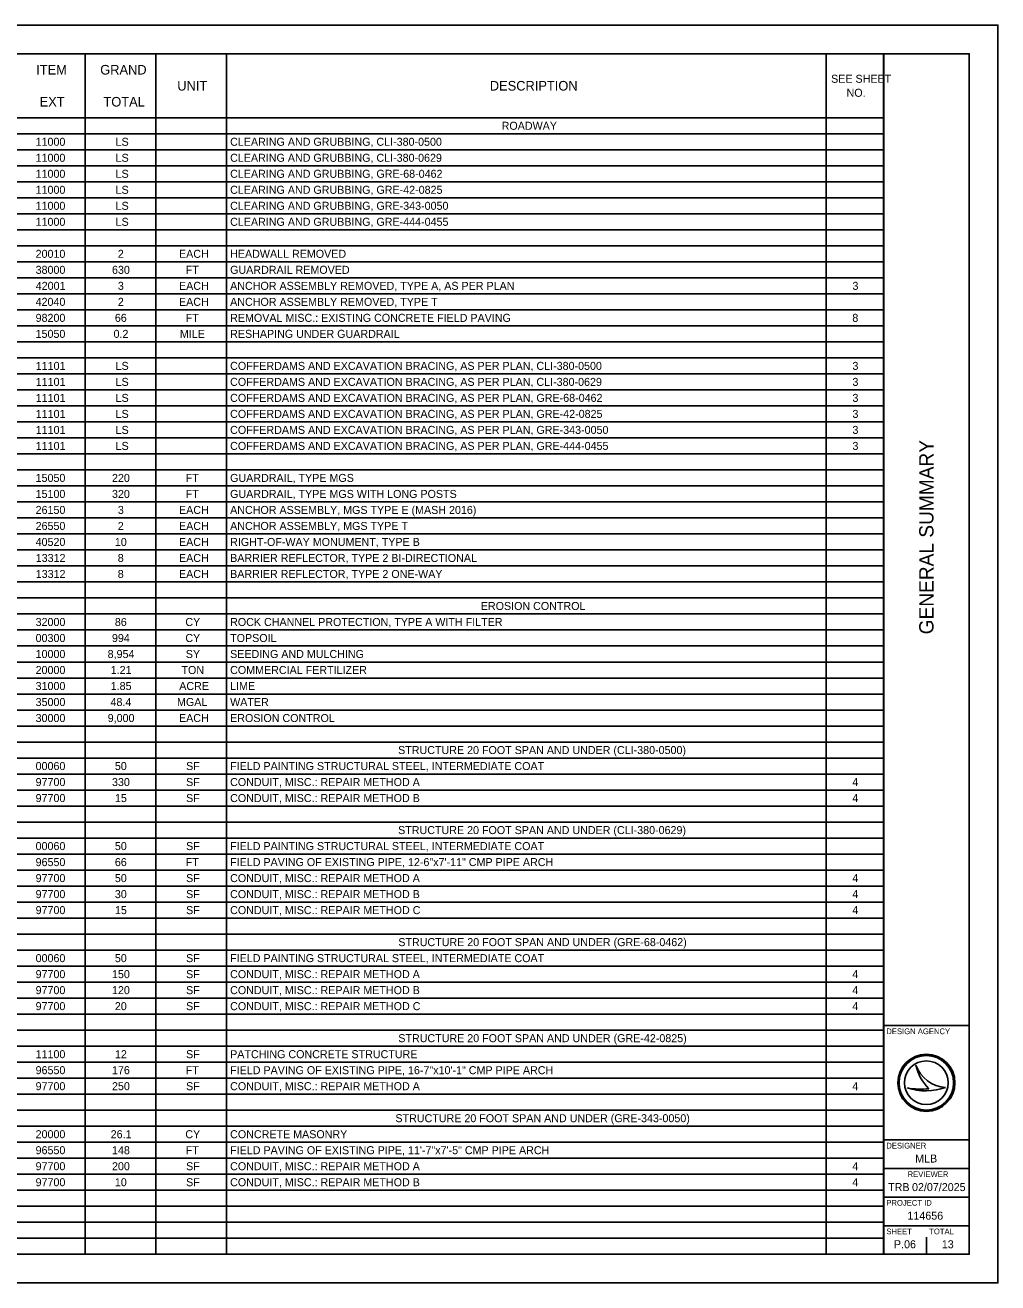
# Model space of a CAD drawing. Extents: x 0 to 34, y 0 to 22.
# Drawn here: x 16.99 to 34, y 0 to 22 of the extents above; entities that cross this region are included whole.
import ezdxf

# ---------------------------------------------------------------- set-up
doc = ezdxf.new("R2010")
doc.units = 0
for name, color, linetype in [('Default', 7, 'Continuous'), ('SH_Border', 7, 'Continuous'), ('SH_Cut_Line', 7, 'Continuous'), ('SH_Data', 7, 'Continuous')]:
    doc.layers.add(name, color=color, linetype=linetype)

msp = doc.modelspace()

# ---------------------------------------------------------------- linework, layer by layer
at = {"layer": 'Default'}
for p, q in [((1.5, 21.5), (32.004, 21.5)), ((18.036, 21.5), (18.036, 0.5)), ((19.272, 21.5), (19.272, 0.5)), ((20.507, 21.5), (20.507, 0.5)), ((30.999, 21.5), (30.999, 0.5)), ((32.004, 21.5), (32.004, 0.5)), ((1.5, 20.38), (32.004, 20.38)), ((1.5, 20.1), (32.004, 20.1)), ((1.5, 19.82), (32.004, 19.82)), ((1.5, 19.54), (32.004, 19.54)), ((1.5, 19.26), (32.004, 19.26)), ((1.5, 18.98), (32.004, 18.98)), ((1.5, 18.7), (32.004, 18.7)), ((1.5, 18.42), (32.004, 18.42)), ((1.5, 18.14), (32.004, 18.14)), ((1.5, 17.86), (32.004, 17.86)), ((1.5, 17.58), (32.004, 17.58)), ((1.5, 17.3), (32.004, 17.3)), ((1.5, 17.02), (32.004, 17.02)), ((1.5, 16.74), (32.004, 16.74)), ((1.5, 16.46), (32.004, 16.46)), ((1.5, 16.18), (32.004, 16.18)), ((1.5, 15.9), (32.004, 15.9)), ((1.5, 15.62), (32.004, 15.62)), ((1.5, 15.34), (32.004, 15.34)), ((1.5, 15.06), (32.004, 15.06)), ((1.5, 14.78), (32.004, 14.78)), ((1.5, 14.5), (32.004, 14.5)), ((1.5, 14.22), (32.004, 14.22)), ((1.5, 13.94), (32.004, 13.94)), ((1.5, 13.66), (32.004, 13.66)), ((1.5, 13.38), (32.004, 13.38)), ((1.5, 13.1), (32.004, 13.1)), ((1.5, 12.82), (32.004, 12.82)), ((1.5, 12.54), (32.004, 12.54)), ((1.5, 12.26), (32.004, 12.26)), ((1.5, 11.98), (32.004, 11.98)), ((1.5, 11.7), (32.004, 11.7)), ((1.5, 11.42), (32.004, 11.42)), ((1.5, 11.14), (32.004, 11.14)), ((1.5, 10.86), (32.004, 10.86)), ((1.5, 10.58), (32.004, 10.58)), ((1.5, 10.3), (32.004, 10.3)), ((1.5, 10.02), (32.004, 10.02)), ((1.5, 9.74), (32.004, 9.74)), ((1.5, 9.46), (32.004, 9.46)), ((1.5, 9.18), (32.004, 9.18)), ((1.5, 8.9), (32.004, 8.9)), ((1.5, 8.62), (32.004, 8.62)), ((1.5, 8.34), (32.004, 8.34)), ((1.5, 8.06), (32.004, 8.06)), ((1.5, 7.78), (32.004, 7.78)), ((1.5, 7.5), (32.004, 7.5)), ((1.5, 7.22), (32.004, 7.22)), ((1.5, 6.94), (32.004, 6.94)), ((1.5, 6.66), (32.004, 6.66)), ((1.5, 6.38), (32.004, 6.38)), ((1.5, 6.1), (32.004, 6.1)), ((1.5, 5.82), (32.004, 5.82)), ((1.5, 5.54), (32.004, 5.54)), ((1.5, 5.26), (32.004, 5.26)), ((1.5, 4.98), (32.004, 4.98)), ((1.5, 4.7), (32.004, 4.7)), ((1.5, 4.42), (32.004, 4.42)), ((1.5, 4.14), (32.004, 4.14)), ((1.5, 3.86), (32.004, 3.86)), ((1.5, 3.58), (32.004, 3.58)), ((1.5, 3.3), (32.004, 3.3)), ((1.5, 3.02), (32.004, 3.02)), ((1.5, 2.74), (32.004, 2.74)), ((1.5, 2.46), (32.004, 2.46)), ((1.5, 2.18), (32.004, 2.18)), ((1.5, 1.9), (32.004, 1.9)), ((1.5, 1.62), (32.004, 1.62)), ((1.5, 1.34), (32.004, 1.34)), ((1.5, 1.06), (32.004, 1.06)), ((1.5, 0.78), (32.004, 0.78)), ((1.5, 0.5), (32.004, 0.5))]:
    msp.add_line(p, q, dxfattribs=at)
at = {"layer": 'SH_Border'}
for p, q in [((32, 0.5), (32, 21.5)), ((32, 4.5), (33.5, 4.5)), ((32, 2.5), (33.5, 2.5)), ((32, 2), (33.5, 2)), ((32, 1.5), (33.5, 1.5)), ((32, 1), (33.5, 1))]:
    msp.add_line(p, q, dxfattribs=at)
msp.add_lwpolyline([(1.5, 21.5), (33.5, 21.5), (33.5, 0.5), (1.5, 0.5)], close=True, dxfattribs=at)
at = {"layer": 'SH_Cut_Line'}
msp.add_lwpolyline([(0, 0), (34, 0), (34, 22), (0, 22)], close=True, dxfattribs=at)
at = {"layer": 'SH_Data'}
for p, q in [((32.567, 3.81), (32.567, 3.81)), ((32.417, 3.41), (32.417, 3.41)), ((32.75, 3.5), (32.75, 3.5)), ((33.087, 3.419), (33.087, 3.419)), ((32.375, 0.675), (32.375, 0.675)), ((32.75, 0.5), (32.75, 0.8))]:
    msp.add_line(p, q, dxfattribs=at)
for radius in [0.5, 0.477, 0.477, 0.382]:
    msp.add_circle((32.75, 3.5), radius, dxfattribs=at)
for centre, radius, start, end in [((33.116, 3.998), 0.58, 198.9257, 198.9319), ((33.347, 3.97), 0.796, 191.6379, 191.6421), ((33.116, 3.998), 0.58, 198.9319, 267.1657), ((33.347, 3.97), 0.796, 191.6421, 226.0947), ((32.739, 4.37), 1.013, 251.4576, 290.0832), ((32.648, 4.654), 1.266, 259.4964, 259.4995), ((32.739, 4.37), 1.013, 251.4527, 251.4576), ((32.648, 4.654), 1.266, 259.4995, 276.6672)]:
    msp.add_arc(centre, radius, start, end, dxfattribs=at)

# ---------------------------------------------------------------- texts
at = {"layer": 'Default'}
for s, height, p in [('ITEM', 0.168, (17.181, 21.136)), ('GRAND', 0.168, (18.301, 21.136)), ('SEE SHEET ', 0.14, (31.084, 20.992)), ('UNIT', 0.168, (19.649, 20.856)), ('DESCRIPTION', 0.168, (25.115, 20.856)), ('EXT', 0.168, (17.242, 20.576)), ('TOTAL', 0.168, (18.357, 20.576)), ('NO.', 0.14, (31.354, 20.747)), ('ROADWAY', 0.14, (25.322, 20.17)), ('11000', 0.14, (17.171, 19.89)), ('LS', 0.14, (18.57, 19.89)), ('CLEARING AND GRUBBING, CLI-380-0500', 0.14, (20.573, 19.89)), ('11000', 0.14, (17.171, 19.61)), ('LS', 0.14, (18.57, 19.61)), ('CLEARING AND GRUBBING, CLI-380-0629', 0.14, (20.573, 19.61)), ('11000', 0.14, (17.171, 19.33)), ('LS', 0.14, (18.57, 19.33)), ('CLEARING AND GRUBBING, GRE-68-0462', 0.14, (20.573, 19.33)), ('11000', 0.14, (17.171, 19.05)), ('LS', 0.14, (18.57, 19.05)), ('CLEARING AND GRUBBING, GRE-42-0825', 0.14, (20.573, 19.05)), ('11000', 0.14, (17.171, 18.77)), ('LS', 0.14, (18.57, 18.77)), ('CLEARING AND GRUBBING, GRE-343-0050', 0.14, (20.573, 18.77)), ('11000', 0.14, (17.171, 18.49)), ('LS', 0.14, (18.57, 18.49)), ('CLEARING AND GRUBBING, GRE-444-0455', 0.14, (20.573, 18.49)), ('20010', 0.14, (17.171, 17.93)), ('2', 0.14, (18.609, 17.93)), ('EACH', 0.14, (19.679, 17.93)), ('HEADWALL REMOVED', 0.14, (20.573, 17.93)), ('38000', 0.14, (17.171, 17.65)), ('630', 0.14, (18.507, 17.65)), ('FT', 0.14, (19.796, 17.65)), ('GUARDRAIL REMOVED', 0.14, (20.573, 17.65)), ('42001', 0.14, (17.173, 17.37)), ('3', 0.14, (18.61, 17.37)), ('EACH', 0.14, (19.679, 17.37)), ('ANCHOR ASSEMBLY REMOVED, TYPE A, AS PER PLAN', 0.14, (20.573, 17.37)), ('3', 0.14, (31.457, 17.37)), ('42040', 0.14, (17.171, 17.09)), ('2', 0.14, (18.609, 17.09)), ('EACH', 0.14, (19.679, 17.09)), ('ANCHOR ASSEMBLY REMOVED, TYPE T', 0.14, (20.573, 17.09)), ('98200', 0.14, (17.171, 16.81)), ('66', 0.14, (18.557, 16.81)), ('FT', 0.14, (19.796, 16.81)), ('REMOVAL MISC.: EXISTING CONCRETE FIELD PAVING', 0.14, (20.573, 16.81)), ('8', 0.14, (31.455, 16.81)), ('15050', 0.14, (17.171, 16.53)), ('0.2', 0.14, (18.534, 16.53)), ('MILE', 0.14, (19.695, 16.53)), ('RESHAPING UNDER GUARDRAIL', 0.14, (20.573, 16.53)), ('11101', 0.14, (17.173, 15.97)), ('LS', 0.14, (18.57, 15.97)), ('COFFERDAMS AND EXCAVATION BRACING, AS PER PLAN, CLI-380-0500', 0.14, (20.573, 15.97)), ('3', 0.14, (31.457, 15.97)), ('11101', 0.14, (17.173, 15.69)), ('LS', 0.14, (18.57, 15.69)), ('COFFERDAMS AND EXCAVATION BRACING, AS PER PLAN, CLI-380-0629', 0.14, (20.573, 15.69)), ('3', 0.14, (31.457, 15.69)), ('11101', 0.14, (17.173, 15.41)), ('LS', 0.14, (18.57, 15.41)), ('COFFERDAMS AND EXCAVATION BRACING, AS PER PLAN, GRE-68-0462', 0.14, (20.573, 15.41)), ('3', 0.14, (31.457, 15.41)), ('11101', 0.14, (17.173, 15.13)), ('LS', 0.14, (18.57, 15.13)), ('COFFERDAMS AND EXCAVATION BRACING, AS PER PLAN, GRE-42-0825', 0.14, (20.573, 15.13)), ('3', 0.14, (31.457, 15.13)), ('11101', 0.14, (17.173, 14.85)), ('LS', 0.14, (18.57, 14.85)), ('COFFERDAMS AND EXCAVATION BRACING, AS PER PLAN, GRE-343-0050', 0.14, (20.573, 14.85)), ('3', 0.14, (31.457, 14.85)), ('11101', 0.14, (17.173, 14.57)), ('LS', 0.14, (18.57, 14.57)), ('COFFERDAMS AND EXCAVATION BRACING, AS PER PLAN, GRE-444-0455', 0.14, (20.573, 14.57)), ('3', 0.14, (31.457, 14.57)), ('15050', 0.14, (17.171, 14.01)), ('220', 0.14, (18.507, 14.01)), ('FT', 0.14, (19.796, 14.01)), ('GUARDRAIL, TYPE MGS', 0.14, (20.573, 14.01)), ('15100', 0.14, (17.171, 13.73)), ('320', 0.14, (18.507, 13.73)), ('FT', 0.14, (19.796, 13.73)), ('GUARDRAIL, TYPE MGS WITH LONG POSTS', 0.14, (20.573, 13.73)), ('26150', 0.14, (17.171, 13.45)), ('3', 0.14, (18.61, 13.45)), ('EACH', 0.14, (19.679, 13.45)), ('ANCHOR ASSEMBLY, MGS TYPE E (MASH 2016)', 0.14, (20.573, 13.45)), ('26550', 0.14, (17.171, 13.17)), ('2', 0.14, (18.609, 13.17)), ('EACH', 0.14, (19.679, 13.17)), ('ANCHOR ASSEMBLY, MGS TYPE T', 0.14, (20.573, 13.17)), ('40520', 0.14, (17.171, 12.89)), ('10', 0.14, (18.557, 12.89)), ('EACH', 0.14, (19.679, 12.89)), ('RIGHT-OF-WAY MONUMENT, TYPE B', 0.14, (20.573, 12.89)), ('13312', 0.14, (17.173, 12.61)), ('8', 0.14, (18.608, 12.61)), ('EACH', 0.14, (19.679, 12.61)), ('BARRIER REFLECTOR, TYPE 2 BI-DIRECTIONAL', 0.14, (20.573, 12.61)), ('13312', 0.14, (17.173, 12.33)), ('8', 0.14, (18.608, 12.33)), ('EACH', 0.14, (19.679, 12.33)), ('BARRIER REFLECTOR, TYPE 2 ONE-WAY', 0.14, (20.573, 12.33)), ('EROSION CONTROL', 0.14, (24.957, 11.77)), ('32000', 0.14, (17.171, 11.49)), ('86', 0.14, (18.557, 11.49)), ('CY', 0.14, (19.79, 11.49)), ('ROCK CHANNEL PROTECTION, TYPE A WITH FILTER', 0.14, (20.573, 11.49)), ('00300', 0.14, (17.171, 11.21)), ('994', 0.14, (18.506, 11.21)), ('CY', 0.14, (19.79, 11.21)), ('TOPSOIL', 0.14, (20.573, 11.21)), ('10000', 0.14, (17.171, 10.93)), ('8,954', 0.14, (18.431, 10.93)), ('SY', 0.14, (19.798, 10.93)), ('SEEDING AND MULCHING', 0.14, (20.573, 10.93)), ('20000', 0.14, (17.171, 10.65)), ('1.21', 0.14, (18.484, 10.65)), ('TON', 0.14, (19.722, 10.65)), ('COMMERCIAL FERTILIZER', 0.14, (20.573, 10.65)), ('31000', 0.14, (17.171, 10.37)), ('1.85', 0.14, (18.484, 10.37)), ('ACRE', 0.14, (19.683, 10.37)), ('LIME', 0.14, (20.573, 10.37)), ('35000', 0.14, (17.171, 10.09)), ('48.4', 0.14, (18.481, 10.09)), ('MGAL', 0.14, (19.644, 10.09)), ('WATER', 0.14, (20.573, 10.09)), ('30000', 0.14, (17.171, 9.81)), ('9,000', 0.14, (18.432, 9.81)), ('EACH', 0.14, (19.679, 9.81)), ('EROSION CONTROL', 0.14, (20.573, 9.81)), ('STRUCTURE 20 FOOT SPAN AND UNDER (CLI-380-0500)', 0.14, (23.511, 9.25)), ('00060', 0.14, (17.171, 8.97)), ('50', 0.14, (18.557, 8.97)), ('SF', 0.14, (19.803, 8.97)), ('FIELD PAINTING STRUCTURAL STEEL, INTERMEDIATE COAT', 0.14, (20.573, 8.97)), ('97700', 0.14, (17.171, 8.69)), ('330', 0.14, (18.507, 8.69)), ('SF', 0.14, (19.803, 8.69)), ('CONDUIT, MISC.: REPAIR METHOD A', 0.14, (20.573, 8.69)), ('4', 0.14, (31.454, 8.69)), ('97700', 0.14, (17.171, 8.41)), ('15', 0.14, (18.559, 8.41)), ('SF', 0.14, (19.803, 8.41)), ('CONDUIT, MISC.: REPAIR METHOD B', 0.14, (20.573, 8.41)), ('4', 0.14, (31.454, 8.41)), ('STRUCTURE 20 FOOT SPAN AND UNDER (CLI-380-0629)', 0.14, (23.511, 7.85)), ('00060', 0.14, (17.171, 7.57)), ('50', 0.14, (18.557, 7.57)), ('SF', 0.14, (19.803, 7.57)), ('FIELD PAINTING STRUCTURAL STEEL, INTERMEDIATE COAT', 0.14, (20.573, 7.57)), ('96550', 0.14, (17.171, 7.29)), ('66', 0.14, (18.557, 7.29)), ('FT', 0.14, (19.796, 7.29)), ('FIELD PAVING OF EXISTING PIPE, 12-6"x7\'-11" CMP PIPE ARCH', 0.14, (20.573, 7.29)), ('97700', 0.14, (17.171, 7.01)), ('50', 0.14, (18.557, 7.01)), ('SF', 0.14, (19.803, 7.01)), ('CONDUIT, MISC.: REPAIR METHOD A', 0.14, (20.573, 7.01)), ('4', 0.14, (31.454, 7.01)), ('97700', 0.14, (17.171, 6.73)), ('30', 0.14, (18.557, 6.73)), ('SF', 0.14, (19.803, 6.73)), ('CONDUIT, MISC.: REPAIR METHOD B', 0.14, (20.573, 6.73)), ('4', 0.14, (31.454, 6.73)), ('97700', 0.14, (17.171, 6.45)), ('15', 0.14, (18.559, 6.45)), ('SF', 0.14, (19.803, 6.45)), ('CONDUIT, MISC.: REPAIR METHOD C', 0.14, (20.573, 6.45)), ('4', 0.14, (31.454, 6.45)), ('STRUCTURE 20 FOOT SPAN AND UNDER (GRE-68-0462)', 0.14, (23.514, 5.89)), ('00060', 0.14, (17.171, 5.61)), ('50', 0.14, (18.557, 5.61)), ('SF', 0.14, (19.803, 5.61)), ('FIELD PAINTING STRUCTURAL STEEL, INTERMEDIATE COAT', 0.14, (20.573, 5.61)), ('97700', 0.14, (17.171, 5.33)), ('150', 0.14, (18.507, 5.33)), ('SF', 0.14, (19.803, 5.33)), ('CONDUIT, MISC.: REPAIR METHOD A', 0.14, (20.573, 5.33)), ('4', 0.14, (31.454, 5.33)), ('97700', 0.14, (17.171, 5.05)), ('120', 0.14, (18.507, 5.05)), ('SF', 0.14, (19.803, 5.05)), ('CONDUIT, MISC.: REPAIR METHOD B', 0.14, (20.573, 5.05)), ('4', 0.14, (31.454, 5.05)), ('97700', 0.14, (17.171, 4.77)), ('20', 0.14, (18.557, 4.77)), ('SF', 0.14, (19.803, 4.77)), ('CONDUIT, MISC.: REPAIR METHOD C', 0.14, (20.573, 4.77)), ('4', 0.14, (31.454, 4.77)), ('STRUCTURE 20 FOOT SPAN AND UNDER (GRE-42-0825)', 0.14, (23.514, 4.21)), ('11100', 0.14, (17.171, 3.93)), ('12', 0.14, (18.559, 3.93)), ('SF', 0.14, (19.803, 3.93)), ('PATCHING CONCRETE STRUCTURE', 0.14, (20.573, 3.93)), ('96550', 0.14, (17.171, 3.65)), ('176', 0.14, (18.507, 3.65)), ('FT', 0.14, (19.796, 3.65)), ('FIELD PAVING OF EXISTING PIPE, 16-7"x10\'-1" CMP PIPE ARCH', 0.14, (20.573, 3.65)), ('97700', 0.14, (17.171, 3.37)), ('250', 0.14, (18.507, 3.37)), ('SF', 0.14, (19.803, 3.37)), ('CONDUIT, MISC.: REPAIR METHOD A', 0.14, (20.573, 3.37)), ('4', 0.14, (31.454, 3.37)), ('STRUCTURE 20 FOOT SPAN AND UNDER (GRE-343-0050)', 0.14, (23.464, 2.81)), ('20000', 0.14, (17.171, 2.53)), ('26.1', 0.14, (18.484, 2.53)), ('CY', 0.14, (19.79, 2.53)), ('CONCRETE MASONRY', 0.14, (20.573, 2.53)), ('96550', 0.14, (17.171, 2.25)), ('148', 0.14, (18.507, 2.25)), ('FT', 0.14, (19.796, 2.25)), ('FIELD PAVING OF EXISTING PIPE, 11\'-7"x7\'-5" CMP PIPE ARCH', 0.14, (20.573, 2.25)), ('97700', 0.14, (17.171, 1.97)), ('200', 0.14, (18.507, 1.97)), ('SF', 0.14, (19.803, 1.97)), ('CONDUIT, MISC.: REPAIR METHOD A', 0.14, (20.573, 1.97)), ('4', 0.14, (31.454, 1.97)), ('97700', 0.14, (17.171, 1.69)), ('10', 0.14, (18.557, 1.69)), ('SF', 0.14, (19.803, 1.69)), ('CONDUIT, MISC.: REPAIR METHOD B', 0.14, (20.573, 1.69)), ('4', 0.14, (31.454, 1.69))]:
    msp.add_text(s, height=height, dxfattribs=at).set_placement(p)
at = {"layer": 'SH_Data'}
msp.add_text('GENERAL SUMMARY', height=0.25, rotation=90, dxfattribs=at).set_placement((32.875, 11.344))
for s, height, p in [('DESIGN AGENCY', 0.1, (32.05, 4.35)), ('DESIGNER', 0.1, (32.05, 2.35)), ('MLB', 0.14, (32.554, 2.105)), ('REVIEWER', 0.1, (32.422, 1.85)), ('TRB', 0.14, (32.081, 1.605)), ('02/07/2025', 0.14, (32.499, 1.605)), ('PROJECT ID', 0.1, (32.05, 1.35)), ('114656', 0.14, (32.419, 1.105)), ('SHEET', 0.1, (32.05, 0.85)), ('TOTAL', 0.1, (32.8, 0.85)), ('P.06', 0.14, (32.183, 0.605)), ('13', 0.14, (33.02, 0.605))]:
    msp.add_text(s, height=height, dxfattribs=at).set_placement(p)

doc.saveas('drawing.dxf')
